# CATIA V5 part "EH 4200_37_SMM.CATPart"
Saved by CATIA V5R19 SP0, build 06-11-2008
Definition: EH 4200_37_SMM
Nomenclature: EH 4200_37_SMM
Description: PART--DESC
Material "Steel": density 7860 kg/m3, Young's modulus 2e+11 Pa, Poisson ratio 0.266, thermal expansion 1.17e-05 1/K
Bounding box of the stored display mesh (mm): x 109.15 to 130.85, y 99.152 to 120.848, z -60 to -20
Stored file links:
  G:\UTB\Kombinované\Bakalářská práce\Catia\FORMA\EH 4200_37_SMM.CATPart
  D:\Aplikace\CATIA\Nová složka\win_b64\startup\materials\Catalog.CATMaterial
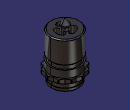
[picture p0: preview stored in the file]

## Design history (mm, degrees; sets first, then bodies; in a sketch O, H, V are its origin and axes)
Set1
  DatumSurface1 "CLOSED_SHELL #15062"
Body1 (main body)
